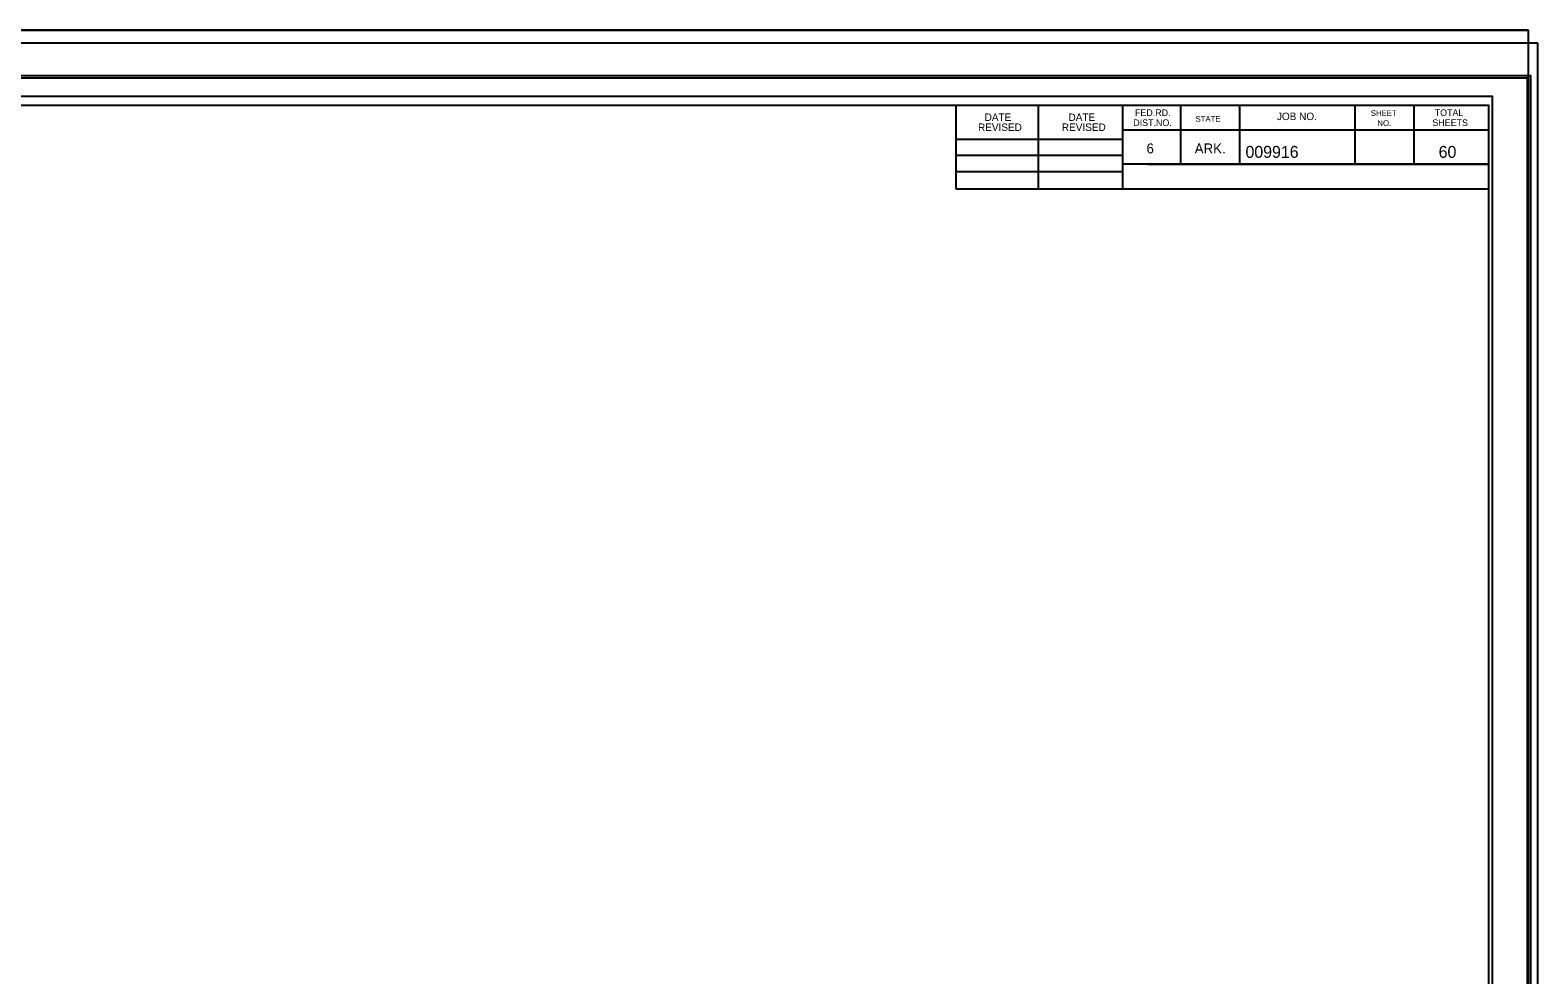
# Model space of a CAD drawing. Extents: x 1369528 to 1373075, y 373809 to 376031.
# Drawn here: x 1371301 to 1373075, y 374920 to 376031 of the extents above; entities that cross this region are included whole.
import ezdxf

# ---------------------------------------------------------------- set-up
doc = ezdxf.new("R2010")
doc.units = 0
for name, color, linetype in [('Level 1', 7, 'Continuous'), ('Plot_Normal', 7, 'Continuous'), ('Plot_PDF', 7, 'Continuous'), ('R_Border', 7, 'Continuous'), ('R_No Plot', 7, 'Continuous')]:
    doc.layers.add(name, color=color, linetype=linetype)

msp = doc.modelspace()

# ---------------------------------------------------------------- linework, layer by layer
at = {"layer": 'Level 1'}
for p in [(1369815.9, 375943.1), (1373017, 373888.5)]:
    msp.add_line(p, (1373017, 375943.1), dxfattribs=at)
at = {"layer": 'Plot_Normal'}
msp.add_lwpolyline([(1369731.4, 375977.8), (1373065.9, 375977.8), (1373065.9, 373853.8), (1369731.4, 373853.8)], close=True, dxfattribs=at)
at = {"layer": 'Plot_PDF'}
msp.add_lwpolyline([(1369726.2, 373859.8), (1373021.5, 373859.8), (1373021.5, 375953.2), (1369726.2, 375953.2)], close=True, dxfattribs=at)
at = {"layer": 'R_Border'}
for p, q in [((1373063.2, 376031.3), (1369527.8, 376031.3)), ((1372390.6, 375844.3), (1372390.6, 375943.1)), ((1372487.4, 375844.3), (1372487.4, 375943.1)), ((1372586, 375943.1), (1372586, 375844.3)), ((1372654.4, 375943.1), (1372654.4, 375873.7)), ((1372723.8, 375943.1), (1372723.8, 375873.7)), ((1372859.6, 375943.1), (1372859.6, 375873.7)), ((1372929, 375943.1), (1372929, 375873.7)), ((1373017, 375913.7), (1372586, 375913.7)), ((1373017, 375913.9), (1373017, 375913.9)), ((1372390.6, 375902.9), (1372586, 375902.9)), ((1372390.6, 375884.3), (1372586, 375884.3)), ((1372390.6, 375864.9), (1372586, 375864.9)), ((1373017, 375873.7), (1372586, 375873.7)), ((1372615.6, 375873.7), (1373017, 375873.7)), ((1373017, 375844.3), (1372390.6, 375844.3))]:
    msp.add_line(p, q, dxfattribs=at)
msp.add_lwpolyline([(1373074.7, 376015.8), (1369674.7, 376015.8), (1369674.7, 373815.8), (1373074.7, 373815.8)], close=True, dxfattribs=at)
at = {"layer": 'R_No Plot'}
for points in [[(1369527.8, 376031.3), (1373063.2, 376031.3), (1373063.2, 373809.4), (1369527.8, 373809.4)], [(1369727.6, 375975), (1373062.1, 375975), (1373062.1, 373865.8), (1369727.6, 373865.8)]]:
    msp.add_lwpolyline(points, close=True, dxfattribs=at)

# ---------------------------------------------------------------- texts
at = {"layer": 'R_Border'}
for s, height, p in [('DATE', 8.79, (1372424, 375924.5)), ('DATE', 8.79, (1372522.6, 375924.5)), ('FED.RD.', 7.82, (1372600.8, 375930.3)), ('JOB NO.', 8.79, (1372767.8, 375925.5)), ('SHEET', 6.84, (1372878.2, 375930.3)), ('TOTAL', 7.82, (1372953.4, 375930.3)), ('REVISED', 8.79, (1372416.2, 375912.7)), ('REVISED', 8.79, (1372514.8, 375912.7)), ('DIST.NO.', 7.82, (1372598.8, 375918.5)), ('STATE', 6.84, (1372672, 375923.5)), ('NO.', 6.84, (1372886, 375918.5)), ('SHEETS', 7.82, (1372950.6, 375918.5)), ('6', 11.7, (1372614.4, 375886.3)), ('ARK.', 11.72, (1372671, 375886.3)), ('009916', 14, (1372730.8, 375881.1)), ('60', 14, (1372958, 375881.1))]:
    msp.add_text(s, height=height, dxfattribs=at).set_placement(p)

doc.saveas('drawing.dxf')
